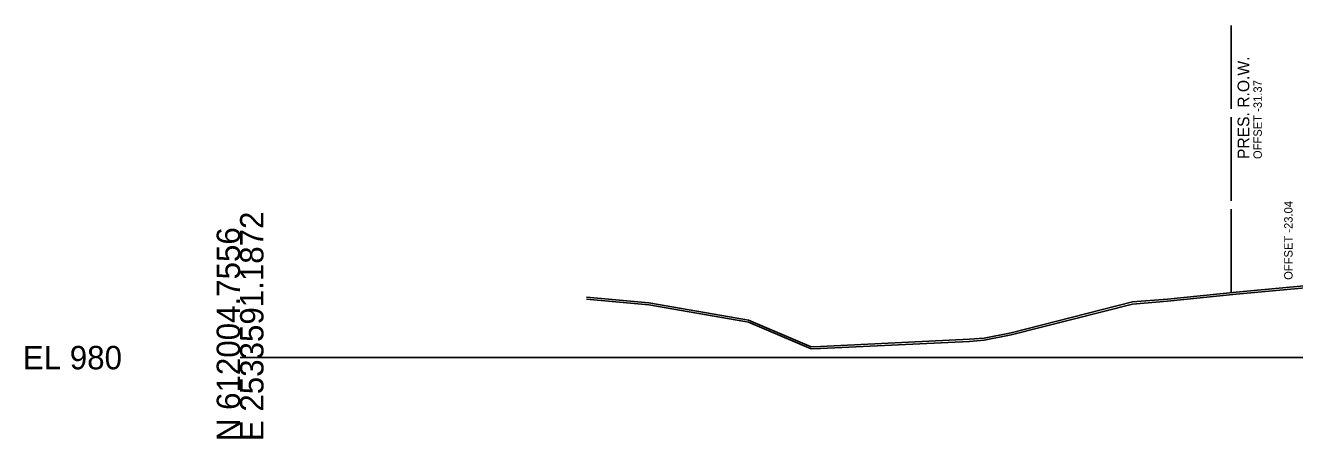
# Model space of a CAD drawing. Extents: x -26 to 303, y -23 to 1542.
# Drawn here: x -25.7 to 126.2, y 490.3 to 539.8 of the extents above; entities that cross this region are included whole.
import ezdxf

# ---------------------------------------------------------------- set-up
doc = ezdxf.new("R2010")
doc.units = 0
for name, color, linetype in [('DESIGN - SHEET - Light Grid', 7, 'Continuous'), ('DESIGN - TYPICAL - Slope Tie Text', 7, 'Continuous'), ('SURVEY - GROUND - Bottom of Topsoil Layer', 7, 'Continuous'), ('SURVEY - GROUND - Top of Ground', 7, 'Continuous'), ('SURVEY - PROPERTY - ROW Lines', 7, 'Continuous'), ('SURVEY - PROPERTY - ROW Lines Text', 7, 'Continuous')]:
    doc.layers.add(name, color=color, linetype=linetype)

msp = doc.modelspace()

# ---------------------------------------------------------------- linework, layer by layer
at = {"layer": 'DESIGN - SHEET - Light Grid'}
msp.add_line((0, 500), (150, 500), dxfattribs=at)
at = {"layer": 'SURVEY - GROUND - Bottom of Topsoil Layer'}
for p, q in [((110.98, 506.76), (119.23, 507.58)), ((119.23, 507.58), (130.77, 508.66)), ((41.45, 506.98), (48.91, 506.3)), ((48.91, 506.3), (60.39, 504.33)), ((92.27, 502.72), (106.82, 506.41)), ((106.82, 506.41), (110.98, 506.76)), ((60.39, 504.33), (60.85, 504.24)), ((60.85, 504.24), (68.33, 501.04)), ((69.45, 501.09), (87.31, 501.95)), ((87.31, 501.95), (89.05, 502.09)), ((89.05, 502.09), (92.27, 502.72)), ((68.33, 501.04), (69.45, 501.09))]:
    msp.add_line(p, q, dxfattribs=at)
at = {"layer": 'SURVEY - GROUND - Top of Ground'}
msp.add_lwpolyline([(41.45, 507.23), (48.91, 506.55), (60.39, 504.58), (60.85, 504.49), (68.33, 501.29), (69.45, 501.34), (87.31, 502.2), (89.05, 502.34), (92.27, 502.97), (106.82, 506.66), (110.98, 507.01), (119.23, 507.83), (130.77, 508.91)], dxfattribs=at)
at = {"layer": 'SURVEY - PROPERTY - ROW Lines'}
for p, q in [((118.63, 529.77), (118.63, 539.77)), ((118.63, 518.77), (118.63, 528.77)), ((118.63, 507.77), (118.63, 517.77))]:
    msp.add_line(p, q, dxfattribs=at)

# ---------------------------------------------------------------- texts
at = {"layer": 'DESIGN - SHEET - Light Grid'}
for s, p in [('E 2533591.1872', (2.8, 490)), ('N 612004.7556', (0, 490))]:
    msp.add_text(s, height=2.8, rotation=90, dxfattribs=at).set_placement(p)
msp.add_text('EL 980', height=2.8, dxfattribs=at).set_placement((-26, 498.6))
at = {"layer": 'DESIGN - TYPICAL - Slope Tie Text'}
msp.add_text('OFFSET -23.04', height=1, rotation=90, dxfattribs=at).set_placement((125.96, 509.31))
at = {"layer": 'SURVEY - PROPERTY - ROW Lines Text'}
for s, height, p in [('PRES. R.O.W.', 1.4, (120.78, 523.77)), ('OFFSET -31.37', 1, (122.28, 523.77))]:
    msp.add_text(s, height=height, rotation=90, dxfattribs=at).set_placement(p)

doc.saveas('drawing.dxf')
